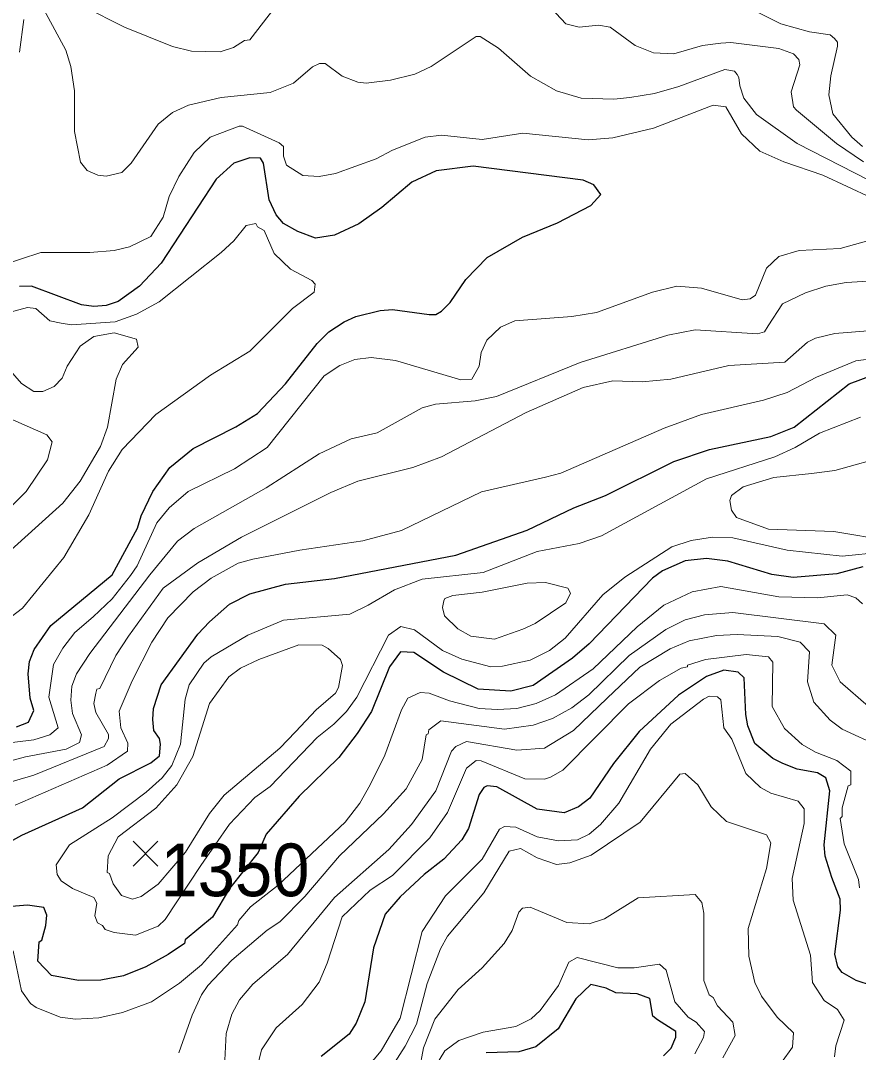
# Model space of a CAD drawing. Extents: x 423 to 448.8, y 7456.3 to 7484.
# Drawn here: x 428.418 to 429.689, y 7465.91 to 7467.476 of the extents above; entities that cross this region are included whole.
import ezdxf
from ezdxf.enums import TextEntityAlignment as Align

# ---------------------------------------------------------------- set-up
doc = ezdxf.new("R2010")
doc.units = 0
doc.header["$LTSCALE"] = 0.032
for name, color, linetype, lineweight in [('1', 7, 'Continuous', 25), ('2', 7, 'Continuous', 13), ('21', 7, 'Continuous', 25)]:
    doc.layers.add(name, color=color, linetype=linetype, lineweight=lineweight)
doc.layers.add('61', color=7, linetype='Continuous')

msp = doc.modelspace()

# ---------------------------------------------------------------- linework, layer by layer
at = {"layer": '1'}
for points in [[(428.4112, 7466.4044), (428.4297, 7466.4113), (428.4375, 7466.4291), (428.432, 7466.4477), (428.429, 7466.4848), (428.4313, 7466.5034), (428.4382, 7466.5219), (428.4637, 7466.5583), (428.5566, 7466.6348), (428.5952, 7466.706), (428.6007, 7466.7246), (428.6185, 7466.7617), (428.644, 7466.798), (428.6795, 7466.8266), (428.7445, 7466.8599), (428.777, 7466.88), (428.8195, 7466.9249), (428.8675, 7466.986), (428.8853, 7467.0038), (428.9085, 7467.0192), (428.9263, 7467.027), (428.9634, 7467.0363), (428.982, 7467.0378), (429.0377, 7467.0301), (429.0477, 7467.0301), (429.0562, 7467.0355), (429.0694, 7467.0486), (429.0933, 7467.0835), (429.1258, 7467.1167), (429.1792, 7467.1476), (429.2326, 7467.1693), (429.2828, 7467.1956), (429.2983, 7467.2126), (429.2875, 7467.2273), (429.2713, 7467.2343), (429.1042, 7467.2552), (429.0485, 7467.2482), (429.0114, 7467.2312), (428.9657, 7467.1925), (428.9309, 7467.1677), (428.8938, 7467.1507), (428.8652, 7467.1461), (428.8381, 7467.1562), (428.8164, 7467.1685), (428.8056, 7467.1817), (428.7948, 7467.2041), (428.7863, 7467.2598), (428.7816, 7467.2675), (428.7654, 7467.2683), (428.7414, 7467.2598), (428.7144, 7467.2358), (428.6308, 7467.1082), (428.5983, 7467.0734), (428.5659, 7467.0502), (428.5473, 7467.044), (428.5287, 7467.0425), (428.5102, 7467.0448), (428.4344, 7467.0734), (428.4158, 7467.0726)], [(428.4196, 7466.24), (428.5117, 7466.2813), (428.5674, 7466.3255), (428.6154, 7466.3494), (428.6285, 7466.3603), (428.6301, 7466.3781), (428.6285, 7466.3866), (428.62, 7466.3989), (428.6185, 7466.4152), (428.6192, 7466.4322), (428.6308, 7466.4678), (428.6865, 7466.5451), (428.7043, 7466.5637), (428.7345, 7466.5907), (428.7654, 7466.6062), (428.8196, 7466.6209), (428.8938, 7466.6294), (429.0779, 7466.665), (429.1862, 7466.7029), (429.2573, 7466.7369), (429.3053, 7466.7555), (429.4089, 7466.8073), (429.4631, 7466.8251), (429.5559, 7466.8452), (429.5915, 7466.8591), (429.675, 7466.9249), (429.7106, 7466.938)], [(429.6959, 7466.6472), (429.6564, 7466.6364), (429.5899, 7466.631), (429.5574, 7466.6356), (429.4909, 7466.6557), (429.4584, 7466.6596), (429.426, 7466.6565), (429.3919, 7466.641), (429.3765, 7466.6302), (429.2805, 7466.5304), (429.255, 7466.5087), (429.1955, 7466.467), (429.1614, 7466.4585), (429.1119, 7466.4616), (429.0593, 7466.4871), (429.0145, 7466.5173), (428.9943, 7466.518), (428.9773, 7466.4956), (428.9502, 7466.4276), (428.9286, 7466.3943), (428.9007, 7466.3579), (428.8404, 7466.2992), (428.7905, 7466.2412), (428.778, 7466.2137), (428.7347, 7466.1588), (428.7087, 7466.1154), (428.6676, 7466.0807), (428.6664, 7466.0756), (428.6417, 7466.0586), (428.6076, 7466.0401), (428.5736, 7466.0261), (428.5396, 7466.0199), (428.5055, 7466.0192), (428.4645, 7466.0269), (428.4437, 7466.0486), (428.446, 7466.078), (428.4498, 7466.0803), (428.456, 7466.1027), (428.4576, 7466.1182), (428.4529, 7466.1298), (428.4282, 7466.1336), (428.3601, 7466.1282)], [(429.7353, 7466.0029), (429.6858, 7466.0192), (429.6642, 7466.0315), (429.658, 7466.04), (429.6533, 7466.0594), (429.6618, 7466.1259), (429.6611, 7466.1429), (429.6487, 7466.1754), (429.6386, 7466.2079), (429.6371, 7466.2249), (429.6456, 7466.3069), (429.6394, 7466.327), (429.6271, 7466.3347), (429.5961, 7466.3402), (429.5745, 7466.3487), (429.5589, 7466.3564), (429.5319, 7466.3788), (429.5211, 7466.4059), (429.518, 7466.4229), (429.5157, 7466.4786), (429.5064, 7466.4871), (429.4847, 7466.4902), (429.4584, 7466.4809), (429.4159, 7466.4523), (429.3563, 7466.3974), (429.3176, 7466.3486), (429.2813, 7466.296), (429.2643, 7466.2829), (429.2426, 7466.2736), (429.2017, 7466.2791), (429.1405, 7466.3131), (429.1259, 7466.3146), (429.1204, 7466.3123), (429.1134, 7466.3015), (429.0972, 7466.2497), (429.0871, 7466.2327), (429.0601, 7466.2032), (429.0299, 7466.18), (428.9936, 7466.146), (428.9711, 7466.1197), (428.9534, 7466.0687), (428.9402, 7465.9867), (428.927, 7465.9542), (428.9162, 7465.9379), (428.8737, 7465.9039)], [(428.3617, 7466.2079), (428.4196, 7466.24)], [(429.3934, 7465.9047), (429.405, 7465.9163), (429.412, 7465.9333), (429.412, 7465.9418), (429.3841, 7465.9596), (429.3772, 7465.965), (429.3726, 7465.9921), (429.3533, 7465.9991), (429.3208, 7466.0006), (429.3061, 7466.0076), (429.2828, 7466.013), (429.2604, 7465.9913), (429.2333, 7465.9457), (429.1993, 7465.9186), (429.1738, 7465.9109), (429.1243, 7465.9093)]]:
    msp.add_lwpolyline(points, dxfattribs=at)
at = {"layer": '2'}
for points in [[(429.6967, 7467.2621), (429.6557, 7467.29), (429.5953, 7467.3403), (429.5907, 7467.3456), (429.5868, 7467.3681), (429.6, 7467.4091), (429.5984, 7467.4176), (429.5907, 7467.4261), (429.5683, 7467.4338), (429.4956, 7467.4431), (429.4801, 7467.4423), (429.4523, 7467.4385), (429.4089, 7467.4261), (429.378, 7467.4276), (429.3502, 7467.4385), (429.3122, 7467.4663), (429.2945, 7467.4694), (429.2651, 7467.4663), (429.2449, 7467.4717), (429.2008, 7467.5189)], [(429.6951, 7467.2853), (429.6789, 7467.2992), (429.6503, 7467.3348), (429.6441, 7467.3635), (429.6472, 7467.3928), (429.6572, 7467.4377), (429.6572, 7467.4439), (429.6525, 7467.4493), (429.6464, 7467.4547), (429.6147, 7467.4593), (429.5714, 7467.4717), (429.4909, 7467.5119)], [(429.3424, 7467.3596), (429.3177, 7467.3572), (429.2682, 7467.3588), (429.231, 7467.3696), (429.1916, 7467.392), (429.1429, 7467.4346), (429.115, 7467.4524), (429.1088, 7467.4524), (429.0408, 7467.4067), (429.016, 7467.3951), (428.9789, 7467.3859), (428.9418, 7467.3812), (428.9294, 7467.3828), (428.9054, 7467.392), (428.8799, 7467.4114), (428.8714, 7467.4114), (428.8605, 7467.406), (428.8319, 7467.3812), (428.7964, 7467.3673), (428.7221, 7467.3596), (428.6726, 7467.348), (428.6479, 7467.3371), (428.6262, 7467.3193), (428.5852, 7467.2598), (428.5713, 7467.2459), (428.5473, 7467.2404), (428.5349, 7467.242), (428.5187, 7467.249), (428.5086, 7467.2613), (428.4993, 7467.3078), (428.4993, 7467.3696), (428.4939, 7467.4068), (428.4862, 7467.4315), (428.4529, 7467.4934)], [(428.8033, 7467.4965), (428.7654, 7467.447), (428.7576, 7467.4462), (428.7407, 7467.4354), (428.7206, 7467.4292), (428.6772, 7467.4299), (428.6479, 7467.4369), (428.5752, 7467.4663), (428.5133, 7467.498)], [(428.4227, 7467.4779), (428.4158, 7467.4284)], [(429.7276, 7467.2226), (429.5961, 7467.2899), (429.5342, 7467.334), (429.5149, 7467.3588), (429.5092, 7467.3774), (429.5078, 7467.3899), (429.5048, 7467.3944), (429.501, 7467.3998), (429.4863, 7467.4021), (429.4167, 7467.3766), (429.3796, 7467.3657), (429.3424, 7467.3596)], [(428.3864, 7467.1043), (428.4483, 7467.1244), (428.5226, 7467.1244), (428.5597, 7467.1275), (428.5828, 7467.133), (428.6153, 7467.1484), (428.6339, 7467.1778), (428.6432, 7467.2095), (428.6579, 7467.2397), (428.6811, 7467.276), (428.7051, 7467.2992), (428.7492, 7467.3162), (428.7546, 7467.3162), (428.8102, 7467.2907), (428.8165, 7467.2853), (428.8165, 7467.2706), (428.8211, 7467.2567), (428.8459, 7467.2412), (428.8706, 7467.2397), (428.8954, 7467.2443), (428.9572, 7467.2667), (428.982, 7467.2799), (429.0315, 7467.2992), (429.0562, 7467.3023), (429.1181, 7467.2961), (429.18, 7467.3054), (429.279, 7467.2954), (429.3161, 7467.2985), (429.378, 7467.3132), (429.4685, 7467.3479), (429.4878, 7467.3456), (429.5118, 7467.3047), (429.5396, 7467.2783), (429.576, 7467.2621), (429.6348, 7467.242), (429.709, 7467.2072)], [(428.4034, 7466.5714), (428.4204, 7466.5846), (428.4831, 7466.6612), (428.521, 7466.7261), (428.5511, 7466.7926), (428.572, 7466.8251), (428.6231, 7466.8785), (428.7058, 7466.938), (428.7654, 7466.9744), (428.8304, 7467.0394), (428.8629, 7467.0641), (428.8644, 7467.0765), (428.8597, 7467.0819), (428.8273, 7467.0989), (428.8025, 7467.1229), (428.787, 7467.1577), (428.777, 7467.1631), (428.7747, 7467.1685), (428.76, 7467.1654), (428.7414, 7467.1422), (428.7221, 7467.1244), (428.6277, 7467.0494), (428.5937, 7467.0308), (428.5612, 7467.0192), (428.4947, 7467.0146), (428.4792, 7467.0169), (428.4622, 7467.0208), (428.4405, 7467.0394), (428.4282, 7467.0409), (428.3447, 7467.0185)], [(429.723, 7467.1476), (429.6611, 7467.1306), (429.5992, 7467.1275), (429.5682, 7467.1183), (429.5497, 7467.1005), (429.5327, 7467.0595), (429.525, 7467.0541), (429.5126, 7467.0525), (429.4507, 7467.0703), (429.4136, 7467.0734), (429.3765, 7467.0641), (429.2914, 7467.0332), (429.2543, 7467.027), (429.1676, 7467.0208), (429.146, 7467.0108), (429.1251, 7466.9914), (429.1166, 7466.9728), (429.1135, 7466.952), (429.1026, 7466.9319), (429.0856, 7466.9311), (428.9866, 7466.9605), (428.9495, 7466.9651), (428.9248, 7466.962), (428.9023, 7466.9527), (428.8783, 7466.9373), (428.7917, 7466.8282), (428.7422, 7466.7957), (428.6718, 7466.7617), (428.6432, 7466.7369), (428.6246, 7466.7138), (428.5945, 7466.6487), (428.5844, 7466.6341), (428.5565, 7466.5985), (428.528, 7466.5714), (428.5001, 7466.5474)], [(428.487, 7466.3703), (428.5071, 7466.3804), (428.5102, 7466.392), (428.4962, 7466.4245), (428.4939, 7466.4446), (428.4955, 7466.4662), (428.5024, 7466.4848), (428.5226, 7466.5157), (428.6138, 7466.6349), (428.6555, 7466.6859), (428.6811, 7466.7052), (428.7902, 7466.7671), (428.8706, 7466.8189), (428.9193, 7466.8413), (428.9588, 7466.8506), (429.0269, 7466.8885), (429.047, 7466.8939), (429.1073, 7466.8994), (429.1398, 7466.9056), (429.2666, 7466.9574), (429.3997, 7466.9991), (429.4414, 7467.0069), (429.5358, 7467.0007), (429.5466, 7467.0038), (429.552, 7467.0131), (429.5737, 7467.0463), (429.6085, 7467.0633), (429.6394, 7467.0734), (429.6704, 7467.0788), (429.7292, 7467.0826)], [(428.8884, 7466.7602), (428.9294, 7466.7772), (429.0129, 7466.798), (429.0562, 7466.8143), (429.1846, 7466.8816), (429.2713, 7466.9195), (429.3161, 7466.9295), (429.361, 7466.928), (429.4043, 7466.9319), (429.4925, 7466.9527), (429.5776, 7466.9581), (429.6116, 7466.9883), (429.624, 7466.9945), (429.6534, 7467.0015), (429.7415, 7467.0084)], [(428.398, 7466.6681), (428.4815, 7466.7439), (428.5078, 7466.7771), (428.5388, 7466.8298), (428.5496, 7466.8592), (428.5627, 7466.9319), (428.5721, 7466.9543), (428.596, 7466.9806), (428.5937, 7466.9929), (428.5597, 7467.0022)], [(428.5597, 7467.0022), (428.5287, 7466.9968), (428.5078, 7466.9821), (428.4885, 7466.952), (428.4807, 7466.9334), (428.4684, 7466.921), (428.4514, 7466.9133), (428.4375, 7466.9133), (428.4189, 7466.9257), (428.3988, 7466.9488)], [(428.4096, 7466.2852), (428.5489, 7466.3463), (428.5798, 7466.3672), (428.5805, 7466.3796), (428.5697, 7466.4028), (428.5674, 7466.4283), (428.5867, 7466.474), (428.6169, 7466.5328), (428.6409, 7466.5699), (428.6795, 7466.6093), (428.7066, 7466.6302), (428.7476, 7466.6526), (428.7701, 7466.6588), (428.8412, 7466.6727), (428.9371, 7466.6866), (428.9959, 7466.7021), (429.1173, 7466.7609), (429.214, 7466.7834), (429.2372, 7466.7895), (429.3942, 7466.8576), (429.4507, 7466.8785), (429.5451, 7466.9001), (429.5807, 7466.9117), (429.6255, 7466.935), (429.685, 7466.9597), (429.7431, 7466.9674)], [(428.3748, 7466.7114), (428.4259, 7466.7617), (428.4583, 7466.8096), (428.4653, 7466.8367), (428.4576, 7466.8475), (428.3802, 7466.8816)], [(428.9449, 7466.5892), (428.9851, 7466.6124), (429.0269, 7466.6286), (429.1197, 7466.6387), (429.2017, 7466.6704), (429.2651, 7466.6828), (429.2991, 7466.6944), (429.4584, 7466.781), (429.5621, 7466.8143), (429.593, 7466.8282), (429.6301, 7466.8499), (429.692, 7466.8746)], [(429.7369, 7466.8166), (429.6534, 7466.7934), (429.6178, 7466.7887), (429.5605, 7466.7826), (429.5141, 7466.7686), (429.4963, 7466.7555), (429.494, 7466.7478), (429.4963, 7466.7331), (429.5041, 7466.7222), (429.5528, 7466.7045), (429.6518, 7466.7006), (429.7361, 7466.6867)], [(428.3787, 7466.3138), (428.4375, 7466.3309), (428.5442, 7466.3742), (428.5511, 7466.3866), (428.5511, 7466.3927), (428.5318, 7466.426), (428.5287, 7466.4399), (428.5318, 7466.4554), (428.5333, 7466.4616), (428.538, 7466.4623), (428.562, 7466.5127), (428.5813, 7466.542), (428.6339, 7466.6147), (428.6865, 7466.6534), (428.753, 7466.6921), (428.8884, 7466.7602)], [(429.7245, 7466.6696), (429.6642, 7466.6634), (429.5807, 7466.6727), (429.4987, 7466.6913), (429.4677, 7466.6921), (429.4352, 7466.6874), (429.4058, 7466.6774), (429.3347, 7466.6317), (429.3014, 7466.6047), (429.2442, 7466.5389), (429.2202, 7466.5203)], [(429.6951, 7466.5908), (429.685, 7466.6), (429.6719, 7466.6047), (429.6271, 7466.6), (429.5683, 7466.6016), (429.4801, 7466.6171), (429.4368, 7466.6093), (429.3935, 7466.5892), (429.3533, 7466.5559), (429.2867, 7466.4925), (429.2295, 7466.4531), (429.2001, 7466.4399), (429.1707, 7466.4322), (429.1413, 7466.4306), (429.1135, 7466.4322), (429.0686, 7466.4438), (429.0377, 7466.4554), (429.0238, 7466.4562), (429.0052, 7466.4476), (428.9959, 7466.4299), (428.9704, 7466.3611), (428.9479, 7466.3162), (428.9324, 7466.2883), (428.91, 7466.2597), (428.8086, 7466.1638), (428.7666, 7466.1308), (428.7486, 7466.1105), (428.7468, 7466.1035), (428.6919, 7466.0431), (428.6587, 7466.0153), (428.6161, 7465.9867), (428.5721, 7465.9704), (428.5365, 7465.9627), (428.5009, 7465.9604), (428.4777, 7465.9635), (428.4413, 7465.9782), (428.4328, 7465.9843), (428.4189, 7466.0037), (428.4065, 7466.064)], [(429.2202, 7466.5203), (429.1908, 7466.5057), (429.1491, 7466.4964), (429.1312, 7466.4956), (429.0872, 7466.5072), (429.0578, 7466.5203), (429.0152, 7466.5513), (428.9944, 7466.5567), (428.9758, 7466.5436), (428.9278, 7466.4492), (428.9124, 7466.4276), (428.893, 7466.4082), (428.8675, 7466.3881), (428.7963, 7466.3138), (428.7731, 7466.2968), (428.7344, 7466.2566), (428.6913, 7466.1939), (428.637, 7466.112), (428.6262, 7466.1019), (428.5922, 7466.088), (428.5597, 7466.0919), (428.5458, 7466.0965), (428.5419, 7466.1027), (428.5341, 7466.1066), (428.5303, 7466.1174), (428.5334, 7466.1367), (428.5287, 7466.1452), (428.4963, 7466.1591), (428.4792, 7466.1707), (428.473, 7466.18), (428.4715, 7466.1947), (428.4916, 7466.2249), (428.5566, 7466.2659), (428.6084, 7466.3053), (428.6324, 7466.327), (428.6471, 7466.3456), (428.6602, 7466.3781), (428.6672, 7466.4461), (428.6733, 7466.4678), (428.6958, 7466.501), (428.7066, 7466.5103), (428.7623, 7466.5436), (428.8165, 7466.566), (428.917, 7466.5753), (428.9449, 7466.5892)], [(429.7044, 7466.4353), (429.6611, 7466.4724), (429.6487, 7466.4979), (429.6549, 7466.5435), (429.6371, 7466.5606), (429.4987, 7466.5776), (429.4553, 7466.5745), (429.426, 7466.5668), (429.3966, 7466.5521), (429.3409, 7466.5126), (429.2797, 7466.4531), (429.2543, 7466.433), (429.2249, 7466.4167), (429.1955, 7466.4067), (429.1522, 7466.4005), (429.0554, 7466.4136), (429.0369, 7466.3997), (429.0361, 7466.3935), (429.033, 7466.3919), (429.0268, 7466.3549), (429.0028, 7466.31), (428.9681, 7466.2721), (428.9015, 7466.2087), (428.849, 7466.1468), (428.811, 7466.1081), (428.7917, 7466.0957), (428.7383, 7466.0501), (428.702, 7466.0114), (428.6919, 7465.9975), (428.678, 7465.9666), (428.6579, 7465.9094)], [(428.5001, 7466.5474), (428.4815, 7466.5235), (428.4676, 7466.4987), (428.4606, 7466.4492), (428.4746, 7466.4028), (428.4622, 7466.392), (428.4375, 7466.3843), (428.3137, 7466.3695)], [(429.7214, 7466.3742), (429.6642, 7466.4005), (429.6464, 7466.4144), (429.6216, 7466.4415), (429.6116, 7466.4724), (429.6147, 7466.518), (429.6008, 7466.5328), (429.5667, 7466.5412), (429.5049, 7466.5443), (429.4739, 7466.5428), (429.4321, 7466.535), (429.4035, 7466.5227), (429.3571, 7466.4948), (429.3076, 7466.4476), (429.2565, 7466.3989)], [(428.7754, 7465.8831), (428.7832, 7465.914), (428.8056, 7465.9472), (428.8451, 7465.9828), (428.8706, 7466.0168), (428.883, 7466.0455), (428.9054, 7466.1158), (428.948, 7466.1561), (428.982, 7466.1785), (429.0384, 7466.2357), (429.0655, 7466.2744), (429.0941, 7466.3417), (429.1088, 7466.3533), (429.1166, 7466.3525), (429.183, 7466.3255), (429.2125, 7466.3247), (429.2218, 7466.3278), (429.2403, 7466.3386), (429.3401, 7466.4392), (429.3872, 7466.4747), (429.4198, 7466.4933), (429.4298, 7466.4956), (429.4298, 7466.4979), (429.4569, 7466.5065), (429.5188, 7466.5142), (429.5528, 7466.5103), (429.559, 7466.5026), (429.5582, 7466.4353), (429.5768, 7466.402), (429.6039, 7466.3773), (429.624, 7466.3657), (429.6564, 7466.3533), (429.6773, 7466.337), (429.6773, 7466.3161), (429.6735, 7466.3146), (429.6642, 7466.2814), (429.6642, 7466.2682), (429.6611, 7466.2651), (429.6673, 7466.2265), (429.6889, 7466.1723), (429.6905, 7466.1599)], [(429.6525, 7465.9032), (429.6549, 7465.9202), (429.6673, 7465.9588), (429.6572, 7465.9751), (429.6371, 7465.989), (429.6193, 7466.016), (429.6162, 7466.0579), (429.5899, 7466.1414), (429.5884, 7466.1739), (429.6069, 7466.2574), (429.6069, 7466.2798), (429.5977, 7466.2914), (429.5559, 7466.3038), (429.5404, 7466.3123), (429.518, 7466.3332), (429.4971, 7466.3858), (429.4847, 7466.4028), (429.4801, 7466.4453), (429.4754, 7466.45), (429.4623, 7466.4508), (429.4538, 7466.4461), (429.4043, 7466.4082), (429.3733, 7466.3703), (429.3254, 7466.2883), (429.2975, 7466.2559), (429.2805, 7466.2411), (429.2627, 7466.2327), (429.2341, 7466.2311), (429.2017, 7466.2373), (429.1692, 7466.252), (429.1522, 7466.2528), (429.1444, 7466.2489), (429.1181, 7466.2033), (429.0624, 7466.1476), (429.0268, 7466.0934), (428.9936, 7465.9619), (428.9649, 7465.9124), (428.9038, 7465.8397)], [(429.2565, 7466.3989), (429.2125, 7466.3719), (429.1707, 7466.3688), (429.0941, 7466.3819), (429.0779, 7466.3742), (429.0717, 7466.3672), (429.0477, 7466.3069), (429.0106, 7466.2559), (428.9765, 7466.2179), (428.8938, 7466.1452), (428.8226, 7466.0586), (428.7701, 7466.0138), (428.7499, 7465.9898), (428.7383, 7465.9681), (428.7298, 7465.9387), (428.7275, 7465.8985)], [(428.3447, 7466.337), (428.4251, 7466.3587), (428.487, 7466.3703)], [(429.5721, 7465.8946), (429.5891, 7465.9178), (429.5907, 7465.9395), (429.5659, 7465.9635), (429.5419, 7465.9952), (429.5319, 7466.0161), (429.5226, 7466.0563), (429.5219, 7466.0981), (429.5497, 7466.1893), (429.5559, 7466.228), (429.5497, 7466.2404), (429.4886, 7466.2605), (429.4654, 7466.2829), (429.4453, 7466.3162), (429.426, 7466.3332), (429.4182, 7466.3324), (429.3579, 7466.2597), (429.2836, 7466.2094), (429.2512, 7466.1978), (429.231, 7466.1955), (429.2017, 7466.2056), (429.1761, 7466.2195), (429.1591, 7466.2156), (429.1204, 7466.1522), (429.0655, 7466.0864), (429.0547, 7466.0671), (429.0346, 7466.0145), (429.0183, 7465.9527), (429.0013, 7465.9194), (428.9564, 7465.849)], [(429.4832, 7465.9016), (429.5018, 7465.9356), (429.4987, 7465.9557), (429.4754, 7465.9805), (429.4685, 7465.9936), (429.4623, 7465.9975), (429.4545, 7466.0192), (429.4545, 7466.1213), (429.4514, 7466.1375), (429.4414, 7466.1499), (429.3548, 7466.1445), (429.3038, 7466.1127), (429.2805, 7466.105), (429.2465, 7466.1074), (429.1908, 7466.1306), (429.1792, 7466.129), (429.1738, 7466.1228), (429.1637, 7466.095), (429.1513, 7466.0756), (429.1181, 7466.0385), (429.0817, 7466.0053), (429.0462, 7465.9604), (429.0291, 7465.9171), (429.016, 7465.8459)], [(429.4406, 7465.9078), (429.4538, 7465.9326), (429.4553, 7465.9418), (429.4429, 7465.9557), (429.4306, 7465.9635), (429.4105, 7465.9867), (429.3973, 7466.0347), (429.3873, 7466.0439), (429.3486, 7466.0385), (429.3239, 7466.0385), (429.262, 7466.054), (429.2496, 7466.047), (429.2341, 7466.0114), (429.2063, 7465.9735), (429.1923, 7465.9612), (429.1692, 7465.9496), (429.1197, 7465.941), (429.0825, 7465.9279), (429.0616, 7465.9124), (429.047, 7465.8892)]]:
    msp.add_lwpolyline(points, dxfattribs=at)
for points in [[(429.18, 7466.5528), (429.1986, 7466.5613), (429.2449, 7466.5923), (429.2519, 7466.607), (429.2481, 7466.6147), (429.214, 7466.6232), (429.1862, 7466.6225), (429.1181, 7466.6086), (429.0733, 7466.6039), (429.0616, 7466.5993), (429.0601, 7466.5954), (429.0578, 7466.5854), (429.0609, 7466.5729), (429.0809, 7466.5529), (429.1011, 7466.542), (429.1367, 7466.5374)], [(428.8845, 7466.5234), (428.8753, 7466.5281), (428.8397, 7466.5289), (428.7793, 7466.5064), (428.7515, 7466.4933), (428.7337, 7466.4801), (428.7043, 7466.4399), (428.6788, 7466.3595), (428.6548, 7466.3162), (428.6231, 7466.2806), (428.5658, 7466.2373), (428.5504, 7466.2087), (428.5488, 7466.1831), (428.5527, 7466.1816), (428.5581, 7466.1661), (428.5705, 7466.1483), (428.5875, 7466.1429), (428.6006, 7466.1468), (428.6262, 7466.1653), (428.6679, 7466.214), (428.7043, 7466.2729), (428.7267, 7466.3007), (428.811, 7466.3719), (428.835, 7466.3966), (428.866, 7466.4299), (428.8953, 7466.4554), (428.9, 7466.4639), (428.9062, 7466.4972), (428.9031, 7466.5064)]]:
    msp.add_lwpolyline(points, close=True, dxfattribs=at)
at = {"layer": '21'}
for p, q in [((428.5884, 7466.2305), (428.6259, 7466.193)), ((428.6259, 7466.2305), (428.5884, 7466.193))]:
    msp.add_line(p, q, dxfattribs=at)

# ---------------------------------------------------------------- texts
at = {"layer": '61', "width": 0.95}
msp.add_text('1350', height=0.08, dxfattribs=at).set_placement((428.7429, 7466.1471), align=Align.CENTER)

doc.saveas('drawing.dxf')
